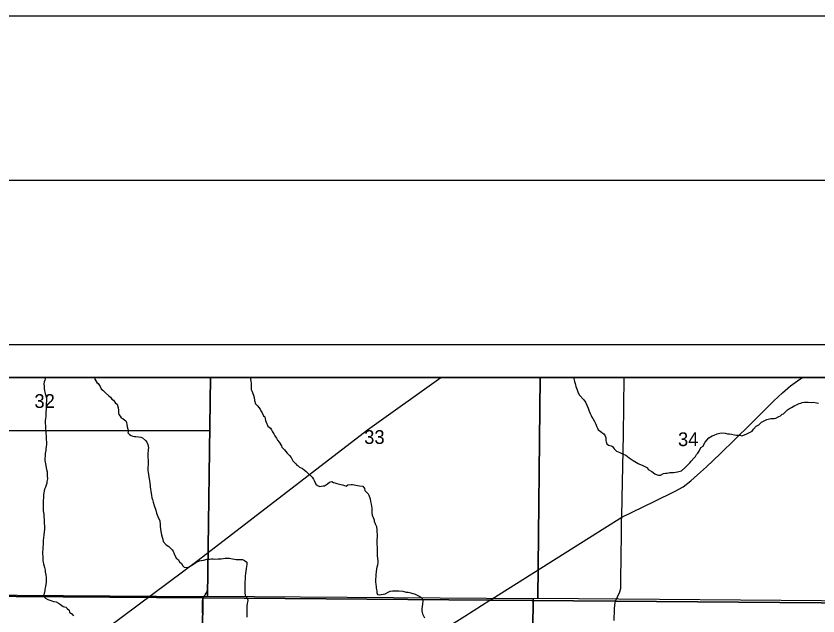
# Model space of a CAD drawing. Extents: x 0 to 34, y 0 to 22.
# Drawn here: x 4.651 to 7.093, y 20.174 to 22 of the extents above; entities that cross this region are included whole.
import ezdxf

# ---------------------------------------------------------------- set-up
doc = ezdxf.new("R2010")
doc.units = 0
for name, color, linetype in [('Default', 7, 'Continuous'), ('GM_X_County_Road', 7, 'Continuous'), ('GM_X_Minor_River', 7, 'Continuous'), ('GM_X_Rail_Line', 7, 'Continuous'), ('GM_X_Section', 7, 'Continuous'), ('GM_X_Section_Text', 7, 'Continuous'), ('GM_X_State_Route', 7, 'Continuous'), ('GM_X_Township_Road', 7, 'Continuous'), ('SH_Border', 7, 'Continuous'), ('SH_Cut_Line', 7, 'Continuous'), ('SH_Data', 7, 'Continuous')]:
    doc.layers.add(name, color=color, linetype=linetype)

msp = doc.modelspace()

# ---------------------------------------------------------------- linework, layer by layer
at = {"layer": 'Default'}
for points in [[(5.2431, 20.9), (4.2372, 20.9), (4.2288, 20.2402), (5.2199, 20.2335), (5.2336, 20.2342)], [(6.2464, 20.9), (5.2431, 20.9), (5.2336, 20.2342), (6.2255, 20.2272), (6.2399, 20.2275)], [(7.2583, 20.9), (6.2464, 20.9), (6.2399, 20.2275), (7.2272, 20.2193), (7.2465, 20.2188)]]:
    msp.add_lwpolyline(points, close=True, dxfattribs=at)
at = {"layer": 'GM_X_County_Road'}
for points in [[(6.4956, 20.4745), (6.4964, 20.532), (6.5, 20.7255), (6.5026, 20.9)], [(6.4807, 20.2288), (6.4819, 20.2315), (6.4891, 20.247), (6.4919, 20.2579), (6.4926, 20.2768), (6.4936, 20.3609), (6.4939, 20.416), (6.4942, 20.4414), (6.4948, 20.4654), (6.4956, 20.4745)], [(6.4715, 20.1596), (6.4728, 20.1945), (6.4737, 20.2075), (6.4765, 20.2185), (6.4773, 20.2216), (6.4807, 20.2288)]]:
    msp.add_lwpolyline(points, dxfattribs=at)
at = {"layer": 'GM_X_Minor_River'}
for points in [[(4.7404, 20.9), (4.738, 20.8917), (4.7361, 20.8863), (4.7358, 20.8806), (4.7362, 20.873), (4.7366, 20.8662), (4.737, 20.859), (4.739, 20.8506), (4.7432, 20.8374), (4.7432, 20.8309)], [(4.8892, 20.9), (4.891, 20.8947), (4.8971, 20.8841), (4.9013, 20.8814), (4.9066, 20.8727), (4.9101, 20.8655), (4.9162, 20.8602), (4.9227, 20.8527), (4.933, 20.8436), (4.9383, 20.8402), (4.9425, 20.8341), (4.9471, 20.8307), (4.9532, 20.822), (4.9589, 20.8183), (4.962, 20.8069), (4.9632, 20.8004), (4.9629, 20.7917), (4.964, 20.7871), (4.9682, 20.7822), (4.9713, 20.7765), (4.9766, 20.7739), (4.985, 20.7679), (4.9873, 20.7626), (4.9885, 20.7565), (4.9896, 20.7496), (4.9916, 20.7424), (4.9927, 20.7383), (4.9916, 20.731), (4.9966, 20.7261), (5.0008, 20.7231), (5.0065, 20.7209), (5.0118, 20.7201), (5.016, 20.7205), (5.024, 20.7194), (5.0312, 20.7179), (5.0361, 20.7164), (5.0449, 20.7077), (5.0491, 20.7032), (5.0525, 20.696), (5.0541, 20.6854), (5.0526, 20.68), (5.0519, 20.6667), (5.0523, 20.6592), (5.0532, 20.6447), (5.0528, 20.6364), (5.0521, 20.6246), (5.0522, 20.6162), (5.0533, 20.6105), (5.0545, 20.6052), (5.0553, 20.5965), (5.0565, 20.5916), (5.0573, 20.5859), (5.0584, 20.5775), (5.0596, 20.5707), (5.0596, 20.5657), (5.0604, 20.5604), (5.0616, 20.5528), (5.0632, 20.5414), (5.0644, 20.5331), (5.0663, 20.5285), (5.0678, 20.5202), (5.0709, 20.5103), (5.0759, 20.4959), (5.0783, 20.4868), (5.0848, 20.4713), (5.0882, 20.4648), (5.0894, 20.4512), (5.0899, 20.4458), (5.0914, 20.4307), (5.0934, 20.4208), (5.0953, 20.4132), (5.0973, 20.4075), (5.0992, 20.4007), (5.1076, 20.3901), (5.1156, 20.3852), (5.1217, 20.3788), (5.1266, 20.3754), (5.1293, 20.3708), (5.132, 20.3625), (5.1385, 20.35), (5.1443, 20.3454), (5.1489, 20.3382), (5.1542, 20.3333), (5.1584, 20.3265)], [(5.3631, 20.9), (5.3632, 20.8996), (5.3659, 20.8886), (5.3663, 20.8821), (5.3667, 20.8764), (5.3667, 20.8681), (5.3671, 20.8635), (5.3683, 20.8586), (5.3737, 20.846), (5.3756, 20.8392), (5.3772, 20.8301), (5.3795, 20.8199), (5.386, 20.8131), (5.3936, 20.8032), (5.3963, 20.7983), (5.4005, 20.7922), (5.404, 20.7831), (5.4082, 20.7801), (5.4093, 20.774), (5.4105, 20.7691), (5.4121, 20.7638), (5.4178, 20.7517), (5.4254, 20.7456), (5.4289, 20.7399), (5.4319, 20.7339), (5.4354, 20.7278), (5.4392, 20.7218), (5.4438, 20.7149), (5.4469, 20.7093), (5.4515, 20.7028), (5.4595, 20.6915), (5.4603, 20.6873), (5.4679, 20.679), (5.4763, 20.6695), (5.4839, 20.662), (5.4885, 20.6559), (5.4935, 20.646), (5.5023, 20.637), (5.5057, 20.6324), (5.5099, 20.6305), (5.5141, 20.6271), (5.5225, 20.6222), (5.5278, 20.6185), (5.5339, 20.6132), (5.5396, 20.6083), (5.5522, 20.5958), (5.5564, 20.5901), (5.558, 20.5859), (5.5637, 20.575), (5.569, 20.5708), (5.5759, 20.5682), (5.5808, 20.569), (5.5861, 20.5701), (5.5903, 20.5701), (5.599, 20.5759), (5.6051, 20.5812), (5.6123, 20.5828), (5.6172, 20.5798), (5.6218, 20.579), (5.6275, 20.5768), (5.6393, 20.5738), (5.6446, 20.5727), (5.6507, 20.5708), (5.656, 20.5693), (5.6609, 20.5728), (5.6708, 20.5736), (5.6757, 20.5736), (5.6799, 20.5732), (5.6856, 20.5717), (5.6905, 20.571), (5.6966, 20.5703), (5.7068, 20.5688), (5.7118, 20.562)], [(6.3486, 20.9), (6.351, 20.8875), (6.3529, 20.8811), (6.3552, 20.872), (6.3598, 20.8617), (6.3621, 20.8526), (6.366, 20.8458), (6.3801, 20.8318), (6.3847, 20.8242), (6.3889, 20.8155), (6.3924, 20.8064), (6.3958, 20.7969), (6.3989, 20.7897), (6.4016, 20.7837), (6.4043, 20.7791), (6.4073, 20.7746), (6.4115, 20.7681), (6.4158, 20.7575), (6.4185, 20.7515), (6.4215, 20.745), (6.4231, 20.7405), (6.428, 20.7375), (6.4341, 20.7325), (6.4402, 20.728), (6.4444, 20.7223), (6.4463, 20.7163), (6.4471, 20.7121), (6.4468, 20.7079), (6.4472, 20.7034), (6.4495, 20.6973), (6.4548, 20.6939), (6.4624, 20.6917), (6.4673, 20.6894), (6.4716, 20.683), (6.4792, 20.6754), (6.4895, 20.6716), (6.4952, 20.6686), (6.502, 20.6649), (6.5077, 20.663), (6.5127, 20.6592), (6.518, 20.6551), (6.5298, 20.6468), (6.5351, 20.6438), (6.545, 20.6377), (6.5496, 20.6358), (6.5568, 20.6332), (6.5671, 20.628), (6.5732, 20.6249), (6.5759, 20.6196), (6.5869, 20.6132), (6.5957, 20.6068), (6.6025, 20.6038), (6.6071, 20.6019), (6.6132, 20.6027), (6.6223, 20.6077), (6.628, 20.6081), (6.6333, 20.6089), (6.6416, 20.6101), (6.653, 20.6105), (6.6648, 20.6121), (6.6769, 20.6152), (6.6867, 20.6251), (6.6961, 20.6339), (6.7026, 20.6396), (6.7067, 20.6449), (6.7143, 20.6545), (6.7196, 20.6594), (6.7226, 20.6655), (6.7271, 20.6694), (6.7312, 20.6758), (6.7357, 20.6865), (6.7426, 20.6903), (6.7452, 20.6957), (6.7493, 20.7029), (6.7603, 20.7162), (6.7656, 20.7193), (6.7705, 20.7224), (6.7766, 20.7239), (6.7853, 20.7285), (6.7936, 20.7305), (6.7982, 20.7309)], [(4.7432, 20.8309), (4.7426, 20.8176), (4.7423, 20.8017), (4.7419, 20.7963), (4.7412, 20.7796), (4.7405, 20.7754), (4.7398, 20.7671), (4.7398, 20.7614), (4.7402, 20.7511), (4.7407, 20.7432), (4.7418, 20.7371), (4.7419, 20.728), (4.7423, 20.7219), (4.7423, 20.7166), (4.7427, 20.7113), (4.7431, 20.7033), (4.7432, 20.6968), (4.7424, 20.6881), (4.7417, 20.6839), (4.7414, 20.6771), (4.7399, 20.6687), (4.7395, 20.663), (4.7385, 20.6508), (4.7381, 20.6467), (4.7393, 20.6421), (4.7408, 20.6368), (4.7439, 20.6197), (4.7455, 20.6121), (4.7459, 20.6045), (4.7459, 20.6003), (4.7463, 20.5916), (4.7449, 20.5829), (4.7445, 20.5775), (4.7408, 20.5658), (4.7378, 20.5597), (4.7348, 20.5433), (4.7345, 20.5365), (4.7338, 20.522), (4.7331, 20.5148), (4.7331, 20.5099), (4.7336, 20.4939), (4.7351, 20.4833), (4.7355, 20.4765), (4.736, 20.4662), (4.7364, 20.4544), (4.7372, 20.4495), (4.7372, 20.4442), (4.7369, 20.4373), (4.7362, 20.4297), (4.7351, 20.4206), (4.7347, 20.4104), (4.7332, 20.4043), (4.7329, 20.3971), (4.7329, 20.3898), (4.7326, 20.3845), (4.7319, 20.3769), (4.7315, 20.3686), (4.7316, 20.3617), (4.7323, 20.3556), (4.7324, 20.3503), (4.7328, 20.3424), (4.7336, 20.3367), (4.7347, 20.3325), (4.7375, 20.3211), (4.7394, 20.3128), (4.7398, 20.3078), (4.7417, 20.2991), (4.7422, 20.2904), (4.7426, 20.285), (4.7422, 20.2755), (4.7411, 20.271), (4.74, 20.263), (4.7389, 20.2554), (4.7382, 20.2512), (4.7352, 20.2379), (4.7345, 20.2337), (4.7402, 20.228), (4.7478, 20.2243), (4.7539, 20.222), (4.76, 20.2194), (4.7653, 20.2179), (4.7733, 20.2168), (4.7801, 20.2123), (4.7862, 20.2085), (4.7946, 20.2025), (4.8022, 20.2002), (4.8064, 20.1961), (4.8121, 20.1919), (4.8137, 20.1858), (4.8205, 20.1798), (4.8255, 20.1737)], [(6.7982, 20.7309), (6.8099, 20.7305), (6.8172, 20.7283), (6.8228, 20.7283), (6.8293, 20.7276), (6.838, 20.725), (6.8441, 20.7242), (6.851, 20.7243), (6.8555, 20.7239), (6.8612, 20.7224), (6.8741, 20.7267), (6.882, 20.7309), (6.8877, 20.7339), (6.8923, 20.7362), (6.8964, 20.7423), (6.9043, 20.7511), (6.9127, 20.7557), (6.9206, 20.7637), (6.9263, 20.7664), (6.9369, 20.7714), (6.9411, 20.7729), (6.949, 20.7745), (6.954, 20.7749), (6.9589, 20.7749), (6.9646, 20.7761), (6.9733, 20.7811), (6.9782, 20.783), (6.9835, 20.7876), (6.9877, 20.7895), (6.9998, 20.8017), (7.0058, 20.8052), (7.0122, 20.8082), (7.0217, 20.8143), (7.0274, 20.8163), (7.0353, 20.8201), (7.0403, 20.822), (7.0448, 20.8236), (7.0513, 20.8247), (7.0577, 20.8244), (7.0623, 20.8244), (7.0725, 20.8237), (7.0786, 20.8241), (7.0881, 20.8226), (7.0942, 20.8215)], [(5.7118, 20.562), (5.7126, 20.5552), (5.7233, 20.5453), (5.7248, 20.5412), (5.7291, 20.5302), (5.7302, 20.5226), (5.7318, 20.5142), (5.733, 20.5081), (5.7338, 20.5024), (5.7342, 20.4933), (5.7342, 20.4876), (5.735, 20.4808), (5.7408, 20.4664), (5.7412, 20.4622), (5.7446, 20.4543), (5.7485, 20.4463), (5.7497, 20.4353), (5.7497, 20.4307), (5.7505, 20.4205), (5.7501, 20.4159), (5.7494, 20.4049), (5.7495, 20.3931), (5.7499, 20.381), (5.7503, 20.3745), (5.75, 20.3669), (5.75, 20.3582), (5.7512, 20.3483), (5.752, 20.3418), (5.752, 20.3362), (5.7509, 20.3285), (5.7498, 20.3225), (5.7487, 20.3168), (5.7473, 20.3076), (5.7465, 20.2997), (5.7462, 20.2928), (5.7455, 20.2867), (5.7455, 20.2776), (5.7459, 20.2693), (5.7471, 20.2632), (5.7475, 20.2586), (5.7483, 20.2545), (5.7491, 20.2499), (5.7495, 20.2438), (5.7518, 20.2393), (5.756, 20.2382), (5.7624, 20.2386), (5.7742, 20.2409), (5.7859, 20.2474), (5.7901, 20.249), (5.7973, 20.2498), (5.8068, 20.2506), (5.8159, 20.2506), (5.8288, 20.2491), (5.839, 20.2465), (5.8447, 20.2458), (5.8527, 20.2439), (5.8592, 20.2425), (5.8641, 20.241), (5.8717, 20.2372), (5.8759, 20.2349), (5.8805, 20.2331), (5.8877, 20.2278), (5.8889, 20.2187), (5.8886, 20.2107), (5.8875, 20.2016), (5.8864, 20.1962), (5.886, 20.1898), (5.8872, 20.1845), (5.8887, 20.1803), (5.8914, 20.1742), (5.8941, 20.1678)], [(5.1584, 20.3265), (5.1626, 20.3227), (5.171, 20.3212), (5.1778, 20.3232), (5.185, 20.3274), (5.1906, 20.3312), (5.1982, 20.337), (5.2024, 20.3385), (5.2092, 20.3416), (5.2149, 20.3423), (5.2213, 20.3439), (5.2327, 20.3466), (5.2395, 20.347), (5.246, 20.3474), (5.2509, 20.3475), (5.2562, 20.3471), (5.2661, 20.3475), (5.2707, 20.3479), (5.2752, 20.348), (5.2817, 20.3484), (5.2873, 20.3495), (5.3006, 20.3492), (5.3052, 20.3489), (5.3098, 20.3477), (5.3162, 20.3462), (5.3212, 20.3455), (5.3306, 20.3459), (5.3356, 20.3452), (5.3398, 20.3452), (5.3462, 20.3426), (5.3531, 20.3373), (5.3535, 20.3305), (5.3528, 20.3248), (5.3513, 20.3187), (5.3506, 20.3088), (5.3498, 20.3042), (5.3487, 20.2936), (5.348, 20.2841), (5.3469, 20.2799), (5.347, 20.2716), (5.3478, 20.259), (5.3474, 20.2537), (5.3478, 20.2446), (5.3486, 20.2374), (5.3506, 20.2332), (5.3559, 20.2264), (5.3563, 20.2211), (5.356, 20.2169), (5.3541, 20.2108), (5.3537, 20.2059), (5.3534, 20.1952), (5.3534, 20.1899), (5.3531, 20.1804), (5.3532, 20.1705)]]:
    msp.add_lwpolyline(points, dxfattribs=at)
at = {"layer": 'GM_X_Rail_Line'}
msp.add_lwpolyline([(2.3438, 17.8832), (2.4082, 17.9379), (2.5423, 18.061), (2.7943, 18.2844), (3.1322, 18.5996), (3.3125, 18.7514), (3.4225, 18.8451), (3.8301, 19.2157), (4.2487, 19.5941), (4.47, 19.794), (4.5566, 19.8598), (4.6465, 19.9302), (4.7011, 19.9679), (5.2057, 20.3431), (5.7213, 20.7403), (5.9437, 20.9)], dxfattribs=at)
at = {"layer": 'GM_X_Section'}
for points in [[(4.2182, 20.2402), (4.2288, 20.2402), (5.2199, 20.2335), (5.2108, 19.1947), (4.2026, 19.2018)], [(5.2199, 20.2335), (5.2336, 20.2342), (6.2255, 20.2272), (6.2144, 19.1838), (5.2108, 19.1947)], [(6.2255, 20.2272), (6.2399, 20.2275), (7.2272, 20.2193), (7.2134, 19.1698), (6.2144, 19.1838)]]:
    msp.add_lwpolyline(points, close=True, dxfattribs=at)
at = {"layer": 'GM_X_State_Route'}
msp.add_lwpolyline([(5.9684, 20.1422), (6.0175, 20.1734), (6.0938, 20.2215), (6.1001, 20.2254), (6.4431, 20.442), (6.4956, 20.4745), (6.5935, 20.5223), (6.6577, 20.5534), (6.6823, 20.5673), (6.7057, 20.5852), (6.7262, 20.6036), (6.7528, 20.6282), (6.7949, 20.6673), (6.8865, 20.7569), (6.9582, 20.8283), (6.9841, 20.8531), (7.0093, 20.8746), (7.0378, 20.8949), (7.0453, 20.9)], dxfattribs=at)
at = {"layer": 'GM_X_Township_Road'}
msp.add_lwpolyline([(8.9, 20.2053), (8.9, 20.9), (3.2412, 20.9), (3.2371, 20.748), (3.2241, 20.2443), (4.224, 20.2365), (5.2207, 20.2288), (6.0936, 20.222), (6.4763, 20.2191), (7.2271, 20.2132)], close=True, dxfattribs=at)
for points in [[(5.241, 20.7384), (5.2424, 20.8678), (5.2427, 20.9)], [(4.2272, 20.7391), (4.2372, 20.739), (4.3538, 20.7384), (5.241, 20.7384)], [(5.2264, 20.238), (5.2293, 20.2427), (5.2326, 20.249), (5.2344, 20.256), (5.2349, 20.2658), (5.2351, 20.3038), (5.241, 20.7384)], [(8.9, 14.1483), (8.9, 20.2053), (7.2271, 20.2132), (6.4763, 20.2191), (6.0936, 20.222), (5.2207, 20.2288), (4.224, 20.2365), (3.2241, 20.2443), (3.2118, 19.2455), (3.2116, 19.2346), (3.2069, 18.535), (3.1896, 17.5787), (3.1895, 17.5705), (3.1894, 17.563), (3.1774, 16.6219), (3.1774, 16.6199), (3.1628, 15.2158), (3.1576, 14.794), (3.1491, 14.2171)], [(5.2027, 17.9498), (5.2148, 19.617), (5.2148, 19.7745), (5.2168, 19.9602), (5.2193, 20.1515), (5.2185, 20.2104), (5.2187, 20.22), (5.2204, 20.2273), (5.2209, 20.2283), (5.2253, 20.2361), (5.2264, 20.238)]]:
    msp.add_lwpolyline(points, dxfattribs=at)
at = {"layer": 'SH_Border'}
msp.add_lwpolyline([(1.5, 21.5), (33.5, 21.5), (33.5, 0.5), (1.5, 0.5)], close=True, dxfattribs=at)
at = {"layer": 'SH_Cut_Line'}
msp.add_lwpolyline([(0, 0), (34, 0), (34, 22), (0, 22)], close=True, dxfattribs=at)
msp.add_lwpolyline([(8.9, 14.1483), (8.9, 20.9), (2.1, 20.9), (2.1, 14.2219)], dxfattribs=at)
at = {"layer": 'SH_Data'}
for p, q in [((2, 21), (9, 21)), ((2.1, 20.9), (8.9, 20.9))]:
    msp.add_line(p, q, dxfattribs=at)

# ---------------------------------------------------------------- texts
at = {"layer": 'GM_X_Section_Text'}
for s, p in [('32', (4.7067, 20.8071)), ('33', (5.7108, 20.6975)), ('34', (6.6662, 20.6908))]:
    msp.add_text(s, height=0.04186, rotation=0, dxfattribs=at).set_placement(p)

doc.saveas('drawing.dxf')
